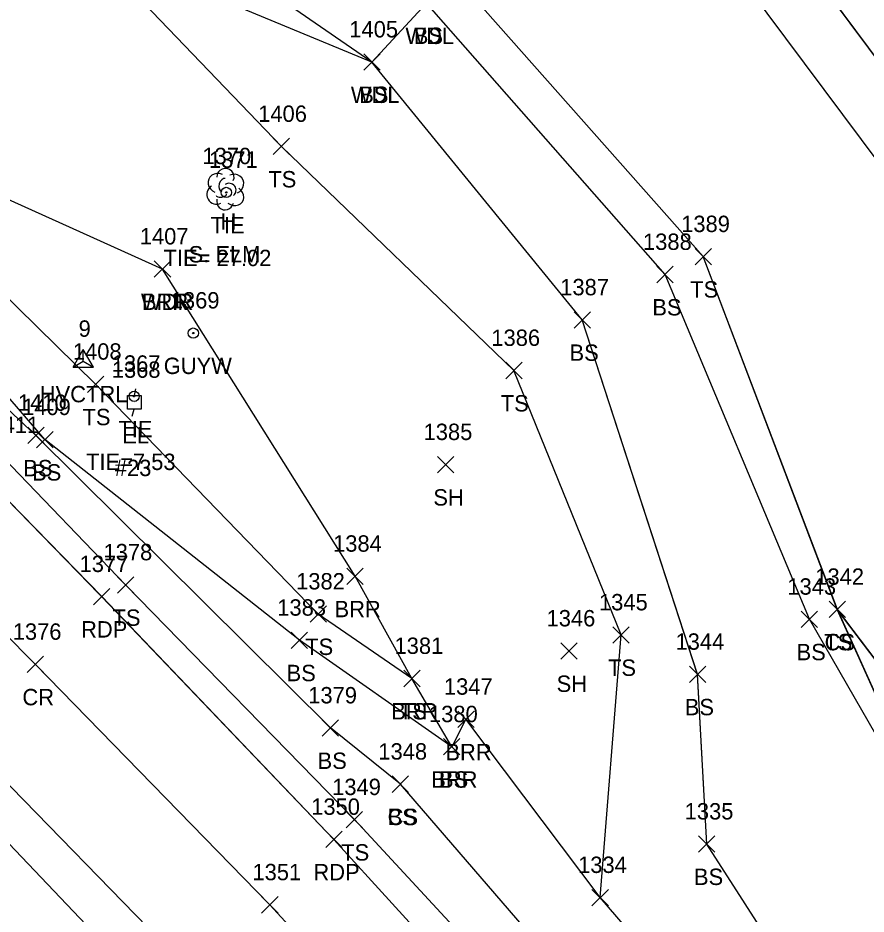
# Model space of a CAD drawing. Extents: x 1415642 to 1422021, y 544543 to 547232.
# Drawn here: x 1416260.5 to 1416364, y 546695.5 to 546804.9 of the extents above; entities that cross this region are included whole.
import ezdxf

# ---------------------------------------------------------------- set-up
doc = ezdxf.new("R2010")
doc.units = 0
for name, color, linetype in [('C_A', 7, 'Continuous'), ('C_C', 7, 'Continuous'), ('C_I', 7, 'Continuous'), ('CBP', 7, 'Continuous'), ('CPSM', 7, 'Continuous'), ('L_A', 7, 'Continuous'), ('L_C', 7, 'Continuous'), ('L_I', 7, 'Continuous'), ('L_TIC', 7, 'Continuous'), ('LABL', 7, 'Continuous'), ('LAWA', 7, 'Continuous'), ('LELB', 7, 'Continuous'), ('LTD', 7, 'Continuous'), ('P_A', 7, 'Continuous'), ('P_I', 7, 'Continuous'), ('P_TIC', 7, 'Continuous'), ('PET', 7, 'Continuous'), ('PRC', 7, 'Continuous'), ('U_A', 7, 'Continuous'), ('U_C', 7, 'Continuous'), ('U_I', 7, 'Continuous'), ('UEPT', 7, 'Continuous'), ('UPGW', 7, 'Continuous')]:
    doc.layers.add(name, color=color, linetype=linetype)

msp = doc.modelspace()

# ---------------------------------------------------------------- linework, layer by layer
at = {"layer": 'CBP'}
for centre, radius in [((1416285.9, 546783.6), 0.625), ((1416285.9, 546783.6), 0.0833), ((1416274.65, 546758.71), 0.625), ((1416274.65, 546758.71), 0.0833)]:
    msp.add_circle(centre, radius, dxfattribs=at)
at = {"layer": 'CPSM'}
for p, q in [((1416267.19, 546762.26), (1416268.44, 546764.42)), ((1416269.69, 546762.26), (1416268.44, 546764.42)), ((1416268.44, 546762.98), (1416268.44, 546764.42)), ((1416267.19, 546762.26), (1416268.44, 546762.98)), ((1416268.44, 546762.98), (1416268.44, 546762.98)), ((1416268.44, 546762.98), (1416269.69, 546762.26)), ((1416267.19, 546762.26), (1416269.69, 546762.26))]:
    msp.add_line(p, q, dxfattribs=at)
at = {"layer": 'L_TIC'}
for points in [[(1416302.68, 546798.52), (1416304.68, 546800.52)], [(1416304.68, 546798.52), (1416302.68, 546800.52)], [(1416302.68, 546798.52), (1416304.68, 546800.52)], [(1416304.68, 546798.52), (1416302.68, 546800.52)], [(1416291.62, 546788.21), (1416293.62, 546790.21)], [(1416293.62, 546788.21), (1416291.62, 546790.21)], [(1416343.12, 546774.76), (1416345.12, 546776.76)], [(1416345.12, 546774.76), (1416343.12, 546776.76)], [(1416277.11, 546773.25), (1416279.11, 546775.25)], [(1416279.11, 546773.25), (1416277.11, 546775.25)], [(1416277.11, 546773.25), (1416279.11, 546775.25)], [(1416279.11, 546773.25), (1416277.11, 546775.25)], [(1416338.46, 546772.58), (1416340.46, 546774.58)], [(1416340.46, 546772.58), (1416338.46, 546774.58)], [(1416328.35, 546767.04), (1416330.35, 546769.04)], [(1416330.35, 546767.04), (1416328.35, 546769.04)], [(1416320, 546760.86), (1416322, 546762.86)], [(1416322, 546760.86), (1416320, 546762.86)], [(1416268.94, 546759.18), (1416270.94, 546761.18)], [(1416270.94, 546759.18), (1416268.94, 546761.18)], [(1416261.67, 546752.94), (1416263.67, 546754.94)], [(1416263.67, 546752.94), (1416261.67, 546754.94)], [(1416262.75, 546752.42), (1416264.75, 546754.42)], [(1416264.75, 546752.42), (1416262.75, 546754.42)], [(1416311.68, 546749.37), (1416313.68, 546751.37)], [(1416313.68, 546749.37), (1416311.68, 546751.37)], [(1416300.62, 546735.74), (1416302.62, 546737.74)], [(1416302.62, 546735.74), (1416300.62, 546737.74)], [(1416272.6, 546734.69), (1416274.6, 546736.69)], [(1416274.6, 546734.69), (1416272.6, 546736.69)], [(1416296.12, 546731.13), (1416298.12, 546733.13)], [(1416298.12, 546731.13), (1416296.12, 546733.13)], [(1416359.48, 546731.7), (1416361.48, 546733.7)], [(1416361.48, 546731.7), (1416359.48, 546733.7)], [(1416359.48, 546731.7), (1416361.48, 546733.7)], [(1416361.48, 546731.7), (1416359.48, 546733.7)], [(1416356.07, 546730.49), (1416358.07, 546732.49)], [(1416358.07, 546730.49), (1416356.07, 546732.49)], [(1416293.82, 546727.93), (1416295.82, 546729.93)], [(1416295.82, 546727.93), (1416293.82, 546729.93)], [(1416333.08, 546728.58), (1416335.08, 546730.58)], [(1416335.08, 546728.58), (1416333.08, 546730.58)], [(1416326.74, 546726.62), (1416328.74, 546728.62)], [(1416328.74, 546726.62), (1416326.74, 546728.62)], [(1416342.42, 546723.77), (1416344.42, 546725.77)], [(1416344.42, 546723.77), (1416342.42, 546725.77)], [(1416307.55, 546723.26), (1416309.55, 546725.26)], [(1416309.55, 546723.26), (1416307.55, 546725.26)], [(1416307.55, 546723.26), (1416309.55, 546725.26)], [(1416309.55, 546723.26), (1416307.55, 546725.26)], [(1416314.15, 546718.28), (1416316.15, 546720.28)], [(1416316.15, 546718.28), (1416314.15, 546720.28)], [(1416297.6, 546717.22), (1416299.6, 546719.22)], [(1416299.6, 546717.22), (1416297.6, 546719.22)], [(1416312.42, 546714.93), (1416314.42, 546716.93)], [(1416314.42, 546714.93), (1416312.42, 546716.93)], [(1416312.42, 546714.93), (1416314.42, 546716.93)], [(1416314.42, 546714.93), (1416312.42, 546716.93)], [(1416306.15, 546710.36), (1416308.15, 546712.36)], [(1416308.15, 546710.36), (1416306.15, 546712.36)], [(1416306.15, 546710.36), (1416308.15, 546712.36)], [(1416308.15, 546710.36), (1416306.15, 546712.36)], [(1416300.53, 546706.03), (1416302.53, 546708.03)], [(1416302.53, 546706.03), (1416300.53, 546708.03)], [(1416343.54, 546703.05), (1416345.54, 546705.05)], [(1416345.54, 546703.05), (1416343.54, 546705.05)], [(1416330.53, 546696.52), (1416332.53, 546698.52)], [(1416332.53, 546696.52), (1416330.53, 546698.52)], [(1416330.53, 546696.52), (1416332.53, 546698.52)], [(1416332.53, 546696.52), (1416330.53, 546698.52)]]:
    msp.add_lwpolyline(points, dxfattribs=at)
at = {"layer": 'LABL'}
for points in [[(1416444.47, 546650.39), (1416449.12, 546622.32), (1416453.47, 546601.16), (1416449.42, 546597.09), (1416447.84, 546594.51), (1416444.98, 546593.05), (1416441.96, 546593.48), (1416418.31, 546638.92), (1416405.03, 546665.65), (1416399.91, 546654.53), (1416396.19, 546650.28), (1416389.66, 546643.26), (1416382.8, 546639.59), (1416370.88, 546651.88), (1416331.53, 546697.52), (1416315.15, 546719.28), (1416313.42, 546715.93), (1416308.55, 546724.26), (1416301.62, 546736.74), (1416278.11, 546774.25)], [(1416444.47, 546650.39), (1416449.12, 546622.32), (1416453.47, 546601.16), (1416449.42, 546597.08), (1416447.84, 546594.51), (1416444.98, 546593.04), (1416441.96, 546593.48), (1416418.31, 546638.92), (1416405.03, 546665.65), (1416399.91, 546654.53), (1416396.19, 546650.28), (1416389.66, 546643.27), (1416382.81, 546639.59), (1416370.88, 546651.88), (1416331.54, 546697.52), (1416315.15, 546719.28), (1416313.42, 546715.93), (1416308.55, 546724.26), (1416301.62, 546736.74), (1416278.12, 546774.25)]]:
    msp.add_lwpolyline(points, dxfattribs=at)
at = {"layer": 'LAWA'}
for points in [[(1416347.35, 546811.63), (1416313.07, 546810.87), (1416310.34, 546806.72), (1416303.68, 546799.52), (1416268.96, 546813.92)], [(1416347.34, 546811.63), (1416313.07, 546810.87), (1416310.34, 546806.72), (1416303.68, 546799.52), (1416268.96, 546813.91)], [(1416278.11, 546774.25), (1416236.51, 546793), (1416219.21, 546811.88)], [(1416278.12, 546774.25), (1416236.51, 546793), (1416219.21, 546811.88)]]:
    msp.add_lwpolyline(points, dxfattribs=at)
at = {"layer": 'LELB'}
for points in [[(1416413.88, 546519.84), (1416385.73, 546558.12), (1416356.85, 546595.36), (1416336.82, 546621.39), (1416300.66, 546661.66), (1416278.22, 546684.25), (1416249.88, 546714.04), (1416230.93, 546728.9), (1416221.86, 546737.5), (1416200.69, 546756.25), (1416176.24, 546778.44), (1416157.26, 546793.38), (1416140.02, 546808.9), (1416121.84, 546825.58), (1416090.2, 546848.7), (1416061.67, 546872.28), (1416021.03, 546902.96), (1415979.27, 546932.57), (1415964.6, 546940.59)], [(1416413.88, 546519.84), (1416385.73, 546558.12), (1416356.85, 546595.36), (1416336.82, 546621.39), (1416300.66, 546661.66), (1416278.22, 546684.25), (1416249.88, 546714.04), (1416230.93, 546728.9), (1416221.87, 546737.51), (1416200.69, 546756.25), (1416176.24, 546778.44), (1416157.26, 546793.38), (1416140.03, 546808.9), (1416121.84, 546825.58), (1416090.21, 546848.7), (1416061.68, 546872.28), (1416021.04, 546902.96), (1415979.28, 546932.57), (1415964.61, 546940.59)], [(1416396.19, 546650.28), (1416389.93, 546664.1), (1416375.33, 546699.79), (1416360.48, 546732.7), (1416344.12, 546775.76), (1416313.07, 546810.87), (1416283.75, 546829.86), (1416246.42, 546852.16), (1416221.38, 546861.32), (1416210.74, 546868.88), (1416211.4, 546870.4), (1416221.96, 546889.07)], [(1416396.19, 546650.28), (1416389.93, 546664.1), (1416375.33, 546699.79), (1416360.49, 546732.7), (1416344.12, 546775.76), (1416313.07, 546810.87), (1416283.75, 546829.86), (1416246.42, 546852.16), (1416221.38, 546861.32), (1416210.75, 546868.87), (1416211.4, 546870.4), (1416221.97, 546889.07)], [(1416399.91, 546654.53), (1416394.35, 546666.38), (1416375.33, 546699.79), (1416357.07, 546731.49), (1416339.46, 546773.58), (1416310.34, 546806.72), (1416282.7, 546825.53), (1416242.81, 546844.04), (1416212.63, 546849.89), (1416203.83, 546852.66), (1416197.94, 546856.2), (1416209.64, 546861.99)], [(1416399.91, 546654.53), (1416394.35, 546666.37), (1416375.33, 546699.79), (1416357.08, 546731.49), (1416339.45, 546773.58), (1416310.34, 546806.72), (1416282.71, 546825.53), (1416242.81, 546844.04), (1416212.62, 546849.89), (1416203.83, 546852.66), (1416197.94, 546856.21), (1416209.64, 546861.99)], [(1416487.57, 546505.93), (1416480.71, 546505.12), (1416469.86, 546502.72), (1416462.76, 546510.55), (1416442.83, 546541.19), (1416430.44, 546560.72), (1416424.35, 546585.18), (1416398.34, 546624.28), (1416389.66, 546643.26), (1416377.3, 546653.03), (1416344.54, 546704.05), (1416343.42, 546724.77), (1416329.35, 546768.04), (1416303.68, 546799.52), (1416274.8, 546819.39), (1416239.26, 546839.41), (1416210.61, 546845.46), (1416203.47, 546849.21), (1416195, 546854.49)], [(1416487.57, 546505.93), (1416480.71, 546505.12), (1416469.86, 546502.72), (1416462.76, 546510.55), (1416442.83, 546541.19), (1416430.44, 546560.72), (1416424.35, 546585.18), (1416398.34, 546624.28), (1416389.66, 546643.27), (1416377.3, 546653.03), (1416344.54, 546704.05), (1416343.42, 546724.76), (1416329.35, 546768.04), (1416303.68, 546799.52), (1416274.8, 546819.4), (1416239.26, 546839.41), (1416210.61, 546845.46), (1416203.48, 546849.21), (1416195, 546854.49)], [(1416307.15, 546711.36), (1416298.6, 546718.22), (1416262.67, 546753.94), (1416226.79, 546787.66), (1416210.45, 546810.14), (1416201.52, 546824.86), (1416194.8, 546838.18), (1416185.88, 546835.28), (1416179.92, 546838.46), (1416184.98, 546843.17), (1416189.86, 546849.7)], [(1416307.15, 546711.36), (1416298.6, 546718.22), (1416262.67, 546753.94), (1416226.79, 546787.66), (1416210.45, 546810.14), (1416201.53, 546824.86), (1416194.8, 546838.18), (1416185.88, 546835.28), (1416179.92, 546838.45), (1416184.98, 546843.16), (1416189.86, 546849.7)], [(1416488.29, 546504.83), (1416488.12, 546506.46), (1416480.5, 546522.11), (1416462.74, 546551.59), (1416447.84, 546594.51), (1416422.44, 546641.16), (1416410.18, 546676.27), (1416393.07, 546713.79), (1416378.8, 546749.63), (1416367.97, 546783.97), (1416347.35, 546811.63), (1416340.26, 546839.45), (1416338.76, 546849.28)], [(1416488.29, 546504.83), (1416488.12, 546506.46), (1416480.5, 546522.11), (1416462.74, 546551.59), (1416447.84, 546594.51), (1416422.44, 546641.16), (1416410.17, 546676.27), (1416393.07, 546713.79), (1416378.8, 546749.63), (1416367.97, 546783.97), (1416347.34, 546811.63), (1416340.26, 546839.45), (1416338.76, 546849.28)], [(1416449.42, 546597.09), (1416431.29, 546645.7), (1416419.63, 546678.87), (1416400.37, 546718.89), (1416388.41, 546748.65), (1416375.25, 546786.59), (1416353.32, 546816.02), (1416347.15, 546837.59)], [(1416449.42, 546597.08), (1416431.29, 546645.7), (1416419.63, 546678.87), (1416400.37, 546718.89), (1416388.42, 546748.65), (1416375.25, 546786.59), (1416353.33, 546816.03), (1416347.15, 546837.59)], [(1416313.42, 546715.93), (1416294.82, 546728.93), (1416263.75, 546753.42), (1416231.45, 546790.98), (1416219.21, 546811.88), (1416212.8, 546833.85)], [(1416313.42, 546715.93), (1416294.82, 546728.93), (1416263.75, 546753.42), (1416231.45, 546790.98), (1416219.21, 546811.88), (1416212.8, 546833.84)], [(1416462.64, 546496.11), (1416437.87, 546538.89), (1416411.19, 546576.82), (1416382.17, 546614.17), (1416360.8, 546639.39), (1416323.65, 546683.15), (1416301.53, 546707.03), (1416273.6, 546735.69), (1416258.67, 546751.22), (1416224.41, 546784.74), (1416201.13, 546806.07), (1416169.09, 546832.26)], [(1416462.64, 546496.11), (1416437.87, 546538.89), (1416411.18, 546576.82), (1416382.17, 546614.17), (1416360.8, 546639.39), (1416323.65, 546683.15), (1416301.53, 546707.03), (1416273.6, 546735.69), (1416258.67, 546751.22), (1416224.4, 546784.74), (1416201.13, 546806.07), (1416169.09, 546832.26)], [(1416331.53, 546697.52), (1416334.08, 546729.58), (1416321, 546761.86), (1416292.62, 546789.21), (1416268.96, 546813.92)], [(1416331.54, 546697.52), (1416334.08, 546729.58), (1416321, 546761.86), (1416292.62, 546789.21), (1416268.96, 546813.91)], [(1416308.55, 546724.26), (1416297.12, 546732.13), (1416269.94, 546760.18), (1416236.51, 546793)], [(1416308.55, 546724.26), (1416297.12, 546732.13), (1416269.94, 546760.18), (1416236.51, 546793)], [(1416405.03, 546665.65), (1416400.36, 546679.1), (1416381.17, 546705.43), (1416360.48, 546732.7)], [(1416405.03, 546665.65), (1416400.36, 546679.1), (1416381.17, 546705.43), (1416360.49, 546732.7)], [(1416430.44, 546560.72), (1416417.31, 546581.34), (1416388.22, 546619.27), (1416367.45, 546645.31), (1416327.63, 546687.63), (1416307.15, 546711.36)], [(1416430.44, 546560.72), (1416417.31, 546581.35), (1416388.22, 546619.27), (1416367.44, 546645.31), (1416327.63, 546687.64), (1416307.15, 546711.36)]]:
    msp.add_lwpolyline(points, dxfattribs=at)
at = {"layer": 'LTD'}
msp.add_line((1416285.76, 546784.05), (1416285.76, 546784.05), dxfattribs=at)
msp.add_line((1416285.76, 546784.05), (1416285.76, 546784.05), dxfattribs=at)
msp.add_arc((1416285.8, 546785.48), 1.05, 335.5272, 180.9563, dxfattribs=at)
for centre, major_axis, ratio, start_param, end_param in [((1416284.96, 546784.71), (1.21, -0.51), 0.895232, 1.570796, 4.712389), ((1416286.8, 546784.63), (-1.14, -0.48), 0.949671, 1.570796, 4.712389), ((1416285.55, 546784.5), (-0.208, -0.792), 0.645439, 3.141593, 6.283185), ((1416286.26, 546783.88), (-0.5, 0.667), 0.989748, 3.141593, 6.283185), ((1416284.67, 546783.34), (0.58, -1.04), 0.959034, 3.141593, 6.283185), ((1416285.3, 546783.3), (-0.625, -0.083), 0.423636, 0, 3.141593), ((1416286.76, 546783.21), (-1.09, 0.79), 0.841452, 1.570796, 4.712389), ((1416285.76, 546782.55), (0.26, 1.06), 0.942809, 1.570796, 4.712389)]:
    msp.add_ellipse(centre, major_axis=major_axis, ratio=ratio, start_param=start_param, end_param=end_param, dxfattribs=at)
at = {"layer": 'P_TIC'}
for points in [[(1416269.68, 546733.26), (1416271.68, 546735.26)], [(1416271.68, 546733.26), (1416269.68, 546735.26)], [(1416261.58, 546724.99), (1416263.58, 546726.99)], [(1416263.58, 546724.99), (1416261.58, 546726.99)], [(1416298.04, 546703.62), (1416300.04, 546705.62)], [(1416300.04, 546703.62), (1416298.04, 546705.62)], [(1416290.21, 546695.63), (1416292.21, 546697.63)], [(1416292.21, 546695.63), (1416290.21, 546697.63)]]:
    msp.add_lwpolyline(points, dxfattribs=at)
at = {"layer": 'PET'}
for points in [[(1416435.56, 546537.44), (1416408.53, 546574.61), (1416379.54, 546611.97), (1416358.62, 546637.86), (1416320.38, 546681.18), (1416299.04, 546704.62), (1416270.68, 546734.26), (1416256.1, 546749.21), (1416221.42, 546781.44), (1416197.8, 546803.68), (1416167.45, 546829.93), (1416146.9, 546847.39), (1416116.66, 546870.72), (1416088.42, 546892.72), (1416062.97, 546911.59), (1416031.6, 546935.61), (1415998.08, 546959.73), (1415969.06, 546981.93), (1415936.64, 547006.92)], [(1416435.56, 546537.44), (1416408.53, 546574.62), (1416379.54, 546611.97), (1416358.63, 546637.85), (1416320.38, 546681.18), (1416299.04, 546704.62), (1416270.69, 546734.26), (1416256.1, 546749.21), (1416221.42, 546781.44), (1416197.8, 546803.68), (1416167.45, 546829.93), (1416146.9, 546847.38), (1416116.66, 546870.72), (1416088.42, 546892.72), (1416062.98, 546911.58), (1416031.6, 546935.61), (1415998.08, 546959.73), (1415969.07, 546981.93), (1415936.65, 547006.92)], [(1416417.68, 546520.98), (1416388.9, 546560.28), (1416359.4, 546597.75), (1416339.06, 546622.92), (1416303.08, 546664.45), (1416282.37, 546687.64), (1416253.58, 546717.16), (1416237.44, 546733.28), (1416206.51, 546762.17), (1416181.86, 546784.67), (1416151.94, 546810.47), (1416130.39, 546828.26), (1416101.49, 546851.34), (1416072.78, 546874.03), (1416047.41, 546892.82), (1416017.81, 546915.59), (1415982.21, 546942.39), (1415954.4, 546964.56)], [(1416417.68, 546520.98), (1416388.9, 546560.28), (1416359.4, 546597.76), (1416339.06, 546622.93), (1416303.08, 546664.45), (1416282.37, 546687.65), (1416253.58, 546717.16), (1416237.44, 546733.28), (1416206.51, 546762.17), (1416181.87, 546784.67), (1416151.94, 546810.47), (1416130.39, 546828.26), (1416101.49, 546851.34), (1416072.78, 546874.03), (1416047.41, 546892.82), (1416017.81, 546915.59), (1415982.21, 546942.39), (1415954.4, 546964.56)]]:
    msp.add_lwpolyline(points, dxfattribs=at)
at = {"layer": 'PRC'}
for points in [[(1416425.29, 546532.23), (1416399.16, 546568.17), (1416370.34, 546605), (1416349.98, 546630.03), (1416312.55, 546673.44), (1416291.21, 546696.63), (1416262.58, 546725.99), (1416246.66, 546742.06), (1416214.68, 546772.43), (1416190.4, 546794.67), (1416160.38, 546819.82), (1416139.01, 546837.64), (1416109.6, 546860.71), (1416080.51, 546883.13), (1416051.44, 546902.01), (1416024.84, 546926.07), (1415989.92, 546951.67), (1415962.46, 546973.18)], [(1416425.29, 546532.24), (1416399.16, 546568.17), (1416370.35, 546605), (1416349.98, 546630.03), (1416312.55, 546673.45), (1416291.21, 546696.63), (1416262.58, 546725.99), (1416246.66, 546742.06), (1416214.67, 546772.43), (1416190.4, 546794.67), (1416160.38, 546819.82), (1416139.01, 546837.64), (1416109.6, 546860.71), (1416080.51, 546883.13), (1416051.45, 546902.01), (1416024.84, 546926.07), (1415989.92, 546951.68), (1415962.46, 546973.18)]]:
    msp.add_lwpolyline(points, dxfattribs=at)
at = {"layer": 'UEPT'}
for p, q in [((1416274.82, 546759.63), (1416274.66, 546758.8)), ((1416273.82, 546757.13), (1416273.82, 546758.8)), ((1416273.82, 546758.8), (1416275.49, 546758.8)), ((1416275.49, 546758.8), (1416275.49, 546757.13)), ((1416275.49, 546757.13), (1416273.82, 546757.13)), ((1416274.41, 546756.3), (1416274.66, 546757.13)), ((1416274.66, 546757.97), (1416274.66, 546757.97))]:
    msp.add_line(p, q, dxfattribs=at)
at = {"layer": 'UPGW'}
for radius in [0.625, 0.0833]:
    msp.add_circle((1416281.87, 546766.43), radius, dxfattribs=at)

# ---------------------------------------------------------------- texts
at = {"layer": 'C_A'}
for s, p in [('TIE', (1416283.98, 546778.6)), ('HVCTRL', (1416263.13, 546757.98)), ('TIE', (1416272.73, 546753.71))]:
    msp.add_text(s, height=2, dxfattribs=at).set_placement(p)
at = {"layer": 'C_C'}
for s, p in [('TIE= 27.02', (1416278.24, 546774.6)), ('TIE=7.53', (1416268.78, 546749.71))]:
    msp.add_text(s, height=2, dxfattribs=at).set_placement(p)
at = {"layer": 'C_I'}
for s, p in [('1371', (1416283.78, 546786.6)), ('9', (1416267.87, 546765.98)), ('1367', (1416271.91, 546761.71))]:
    msp.add_text(s, height=2, dxfattribs=at).set_placement(p)
at = {"layer": 'L_A'}
for s, p in [('WDL', (1416307.76, 546801.72)), ('BS', (1416308.78, 546801.72)), ('WDL', (1416301.1, 546794.52)), ('BS', (1416302.12, 546794.52)), ('TS', (1416291.03, 546784.21)), ('H', (1416285.19, 546779.05)), ('TS', (1416342.53, 546770.76)), ('WDR', (1416275.48, 546769.25)), ('BRR', (1416275.6, 546769.25)), ('BS', (1416337.9, 546768.58)), ('BS', (1416327.79, 546763.04)), ('TS', (1416319.4, 546756.86)), ('TS', (1416268.35, 546755.18)), ('BS', (1416261.11, 546748.94)), ('BS', (1416262.19, 546748.42)), ('SH', (1416311.17, 546745.37)), ('BRR', (1416299.11, 546731.74)), ('TS', (1416272.01, 546730.69)), ('TS', (1416358.89, 546727.7)), ('CS', (1416358.93, 546727.7)), ('TS', (1416295.53, 546727.13)), ('BS', (1416355.51, 546726.49)), ('TS', (1416332.49, 546724.58)), ('BS', (1416293.26, 546723.93)), ('SH', (1416326.22, 546722.62)), ('BRR', (1416306.04, 546719.26)), ('TS', (1416306.96, 546719.26)), ('BS', (1416341.86, 546719.77)), ('BRR', (1416312.64, 546714.28)), ('BS', (1416297.04, 546713.22)), ('BRR', (1416310.91, 546710.93)), ('BS', (1416311.86, 546710.93)), ('CS', (1416305.59, 546706.36)), ('BS', (1416305.59, 546706.36)), ('TS', (1416299.93, 546702.03)), ('BS', (1416342.98, 546699.05))]:
    msp.add_text(s, height=2, dxfattribs=at).set_placement(p)
at = {"layer": 'L_C'}
msp.add_text('S. ELM', height=2, dxfattribs=at).set_placement((1416281.3, 546775.05))
at = {"layer": 'L_I'}
for s, p in [('1405', (1416300.91, 546802.52)), ('1405', (1416300.91, 546802.52)), ('1406', (1416289.79, 546792.21)), ('1370', (1416282.98, 546787.05)), ('1389', (1416341.42, 546778.76)), ('1407', (1416275.34, 546777.25)), ('1407', (1416275.34, 546777.25)), ('1388', (1416336.76, 546776.58)), ('1387', (1416326.66, 546771.04)), ('1386', (1416318.25, 546764.86)), ('1408', (1416267.17, 546763.18)), ('1410', (1416260.46, 546756.94)), ('1409', (1416260.97, 546756.42)), ('1411', (1416257.11, 546754.22)), ('1385', (1416309.98, 546753.37)), ('1384', (1416298.93, 546739.74)), ('1378', (1416270.91, 546738.69)), ('1342', (1416357.79, 546735.7)), ('1342', (1416357.79, 546735.7)), ('1382', (1416294.42, 546735.13)), ('1343', (1416354.38, 546734.49)), ('1345', (1416331.39, 546732.58)), ('1383', (1416292.12, 546731.93)), ('1346', (1416324.99, 546730.62)), ('1344', (1416340.73, 546727.77)), ('1381', (1416306.43, 546727.26)), ('1381', (1416306.43, 546727.26)), ('1347', (1416312.46, 546722.28)), ('1379', (1416295.9, 546721.22)), ('1380', (1416310.64, 546718.93)), ('1380', (1416310.64, 546718.93)), ('1348', (1416304.46, 546714.36)), ('1348', (1416304.46, 546714.36)), ('1349', (1416298.82, 546710.03)), ('1335', (1416341.85, 546707.05)), ('1334', (1416328.84, 546700.52)), ('1334', (1416328.84, 546700.52))]:
    msp.add_text(s, height=2, dxfattribs=at).set_placement(p)
at = {"layer": 'P_A'}
for s, p in [('RDP', (1416268.17, 546729.26)), ('CR', (1416261.01, 546720.99)), ('RDP', (1416296.53, 546699.62))]:
    msp.add_text(s, height=2, dxfattribs=at).set_placement(p)
at = {"layer": 'P_I'}
for s, p in [('1377', (1416267.99, 546737.26)), ('1376', (1416259.83, 546728.99)), ('1350', (1416296.26, 546707.62)), ('1351', (1416289.09, 546699.63))]:
    msp.add_text(s, height=2, dxfattribs=at).set_placement(p)
at = {"layer": 'U_A'}
for s, p in [('GUYW', (1416278.26, 546761.43)), ('EL', (1416273.19, 546752.97))]:
    msp.add_text(s, height=2, dxfattribs=at).set_placement(p)
at = {"layer": 'U_C'}
msp.add_text('#23', height=2, dxfattribs=at).set_placement((1416272.29, 546748.97))
at = {"layer": 'U_I'}
for s, p in [('1369', (1416279.12, 546769.43)), ('1368', (1416271.92, 546760.97))]:
    msp.add_text(s, height=2, dxfattribs=at).set_placement(p)

doc.saveas('drawing.dxf')
